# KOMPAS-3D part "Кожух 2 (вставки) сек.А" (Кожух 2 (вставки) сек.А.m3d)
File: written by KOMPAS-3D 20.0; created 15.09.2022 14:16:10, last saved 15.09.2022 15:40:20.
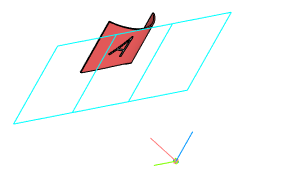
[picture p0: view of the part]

Document properties: Полное имя файла: D:\YAKOVLEV\ПРОЕКТЫ\ДЦ-2. ДП-7 Газопровод Окожушивание\ПРОБА Соединение труб. Окожушивание\Кожух 2 (вставки) сек.А.m3d

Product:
- Part/product: Кожух 2 (вставки) сек.А
    Материал: Сталь 45  ГОСТ 1050-2013 (density 7810 kg/m3)
    Масса: 73.9329

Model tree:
1. Эскиз:1  (with: Смещенная плоскость:1, Обечайка:1)  (labels: Кожух 2 (вставки))
2. Обечайка:1  (labels: Кожух 1 (трубы); Кожух 2 (вставки))
     Расстояние 1 = 823.908
3. Сгиб(1) - Обечайка:1
     Радиус сгиба = 530; Коэффициент = 0.5; Величина сгиба = 10; Зазор = 0.01; Угол = 180; Параметр U, % = 11; Длина = 366.31
4. Касательная плоскость:1  (with: Обечайка:1)
5. Разогнуть:1  (with: Обечайка:1)
6. Смещенная плоскость:1  (with: Обечайка:1)
     Расстояние = 0.1
7. Эскиз:3  (with: Обечайка:1)
8. Вырез в листовом теле:3
     Глубина выреза = 100
9. Элемент выдавливания:1
     Расстояние 2 = 20
10. Эскиз:4  (with: Обечайка:1, Вырез в листовом теле:3)
11. Вырез в листовом теле:4
     Глубина выреза = 100
12. Эскиз:5  (with: Обечайка:1)
13. Вырез в листовом теле:5
     Глубина выреза = 10
14. Эскиз:6  (with: Обечайка:1)
15. Вырез в листовом теле:6
     Глубина выреза = 0.1
16. Фаска:1  (with: Вырез в листовом теле:5)
     Угол = 20; Длина 1 = 14; Длина 2 = 5.09558
17. Согнуть:1  (with: Обечайка:1)
18. Развертка  (labels: Сталь 45  ГОСТ 1050-2013)

Expressions: v172*2
Referenced files in D:\YAKOVLEV\ПРОЕКТЫ\ДЦ-2. ДП-7 Газопровод Окожушивание\ПРОБА Соединение труб. Окожушивание\: Соединение труб. Окожушивание -2.a3d
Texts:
  Соединение труб. Окожушивание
